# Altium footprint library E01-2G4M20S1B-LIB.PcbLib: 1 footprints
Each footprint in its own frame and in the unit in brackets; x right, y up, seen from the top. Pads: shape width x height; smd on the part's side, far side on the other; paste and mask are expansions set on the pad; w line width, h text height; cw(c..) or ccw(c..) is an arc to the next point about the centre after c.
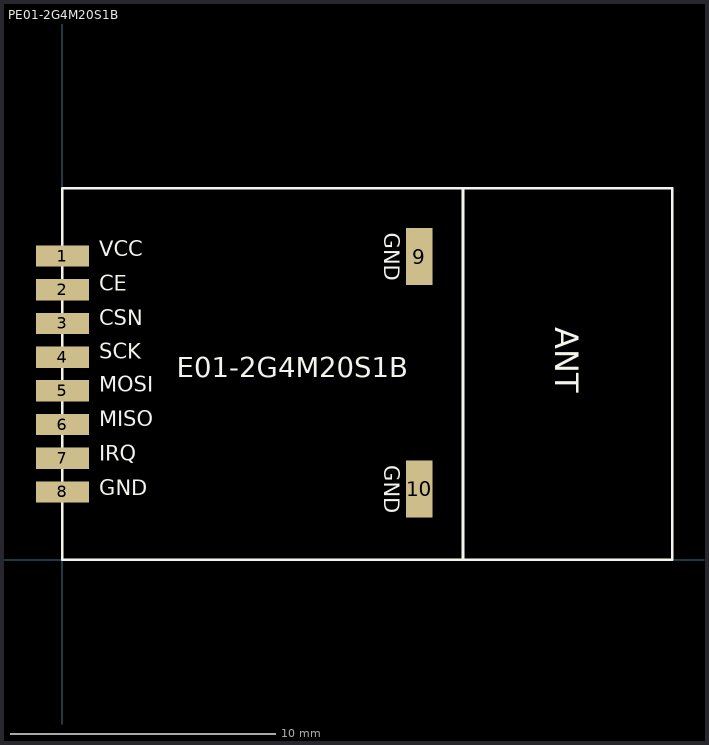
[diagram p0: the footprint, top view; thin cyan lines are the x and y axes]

## PE01-2G4M20S1B [mm] "23*14mm-S"
pads (10):
  rect 2x0.8 smd: 1(0,11.445) 2(0,10.175) 3(0,8.905) 4(0,7.635) 5(0,6.365) 6(0,5.095) 7(0,3.825) 8(0,2.555)
  rect 1x2.15 smd: 9(13.462,11.43) 10(13.462,2.667)
Top Overlay:
  lines w0.1: 15.113,0 15.113,13.97 ; 0,0 0,14 23,14 23,0 0,0
  text "VCC" at 1.391,11.227 h1
  text "CE" at 1.391,9.927 h1
  text "CSN" at 1.391,8.627 h1
  text "SCK" at 1.397,7.366 h1
  text "MOSI" at 1.391,6.127 h1
  text "MISO" at 1.391,4.827 h1
  text "IRQ" at 1.391,3.527 h1
  text "GND" at 1.391,2.227 h1
  text "E01-2G4M20S1B" at 4.318,6.604 h1.3
  text "ANT" at 18.288,8.763 h1.5
  text "GND" at 11.938,12.319 h1
  text "GND" at 11.938,3.556 h1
